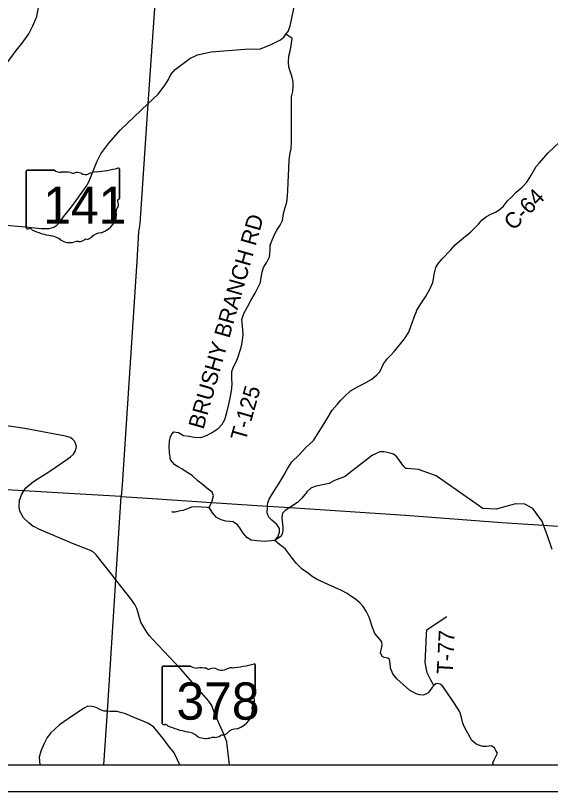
# Model space of a CAD drawing. Extents: x 0 to 34, y 0 to 22.
# Drawn here: x 4.206 to 6.219, y 14 to 16.922 of the extents above; entities that cross this region are included whole.
import ezdxf

# ---------------------------------------------------------------- set-up
doc = ezdxf.new("R2010")
doc.units = 0
for name, color, linetype in [('GM_X_County_Road', 7, 'Continuous'), ('GM_X_County_Road_Text', 7, 'Continuous'), ('GM_X_State_Route', 7, 'Continuous'), ('GM_X_State_Shield', 7, 'Continuous'), ('GM_X_Township', 7, 'Continuous'), ('GM_X_Township_Road', 7, 'Continuous'), ('GM_X_Township_Road_Text', 7, 'Continuous'), ('SH_Data', 7, 'Continuous'), ('SH_Masking', 7, 'Continuous')]:
    doc.layers.add(name, color=color, linetype=linetype)

msp = doc.modelspace()

# ---------------------------------------------------------------- linework, layer by layer
at = {"layer": 'GM_X_County_Road'}
for points in [[(4.0336, 16.5466), (4.0388, 16.5536), (4.0613, 16.5797), (4.0854, 16.6142), (4.1095, 16.6497), (4.1485, 16.7065), (4.1848, 16.7572), (4.2085, 16.7901), (4.231, 16.8177), (4.2555, 16.8525), (4.2704, 16.8828), (4.2862, 16.9173), (4.2952, 16.9655)], [(5.7143, 15.8076), (5.7144, 15.8078), (5.7163, 15.8125), (5.7312, 15.8359), (5.7484, 15.862), (5.7664, 15.8931), (5.7764, 15.9166), (5.783, 15.9522), (5.7881, 15.9723), (5.7946, 15.9852), (5.8118, 16.0056), (5.8434, 16.0397), (5.8602, 16.0582), (5.877, 16.0721), (5.8915, 16.085), (5.9185, 16.1053), (5.9483, 16.136), (5.9608, 16.1507), (5.9776, 16.1647), (5.994, 16.1741), (6.0126, 16.1812), (6.024, 16.1884), (6.0419, 16.2038), (6.0576, 16.2235), (6.074, 16.239), (6.0904, 16.2567), (6.1121, 16.2749), (6.13, 16.2941), (6.1415, 16.3116), (6.1645, 16.3532), (6.1774, 16.3668), (6.2103, 16.4042), (6.2518, 16.4439)], [(5.1525, 15.0518), (5.1525, 15.0521), (5.1536, 15.0684), (5.1541, 15.0746), (5.1552, 15.0862), (5.1598, 15.101), (5.1782, 15.1298), (5.1981, 15.1608), (5.2168, 15.1926), (5.2264, 15.2115), (5.2452, 15.2411), (5.2718, 15.2656), (5.2966, 15.2932), (5.3267, 15.3212), (5.3451, 15.3495), (5.373, 15.3957), (5.3972, 15.4355), (5.4159, 15.4574), (5.43, 15.4729), (5.4449, 15.4884), (5.4658, 15.5088), (5.4947, 15.525), (5.5179, 15.5359), (5.5465, 15.5528), (5.5659, 15.5683), (5.5762, 15.5796), (5.5911, 15.6099), (5.6053, 15.63), (5.6179, 15.6428), (5.6316, 15.6576), (5.6694, 15.7037), (5.6858, 15.7298), (5.6939, 15.7503), (5.7055, 15.7863), (5.7143, 15.8076)], [(6.0042, 14.1), (6.0021, 14.1076), (6.0067, 14.1193), (6.0197, 14.1447), (6.0137, 14.1546), (6.0077, 14.1649), (5.9956, 14.1718), (5.9786, 14.1689), (5.9645, 14.1697), (5.9524, 14.1732), (5.9384, 14.1797), (5.9229, 14.1923), (5.8944, 14.2441), (5.8892, 14.2567), (5.884, 14.2788), (5.8777, 14.2993), (5.8574, 14.3317), (5.8258, 14.3774), (5.8115, 14.3988), (5.8032, 14.4038), (5.7956, 14.4061), (5.7869, 14.405), (5.7804, 14.3988), (5.775, 14.3937), (5.764, 14.3781), (5.759, 14.3713), (5.7502, 14.3661), (5.74, 14.3631), (5.7263, 14.3635), (5.7135, 14.3674), (5.6878, 14.3812), (5.6406, 14.4236), (5.6263, 14.4434), (5.6173, 14.4644), (5.6155, 14.4826), (5.6129, 14.4963), (5.6065, 14.5016), (5.5933, 14.5044), (5.585, 14.5086), (5.579, 14.5215), (5.5836, 14.5386), (5.5856, 14.5515), (5.5841, 14.5618), (5.5804, 14.5686), (5.5578, 14.5946), (5.5488, 14.6178), (5.5365, 14.6558), (5.5252, 14.6787), (5.5143, 14.6958), (5.5019, 14.7103), (5.4857, 14.7245), (5.4672, 14.7356), (5.4539, 14.7451), (5.432, 14.7566), (5.3844, 14.7774), (5.3409, 14.7985), (5.3227, 14.8092), (5.3084, 14.8211), (5.285, 14.8368), (5.2733, 14.8486), (5.2616, 14.8597), (5.2484, 14.8776), (5.2334, 14.8974), (5.2221, 14.9119), (5.2126, 14.9192), (5.1994, 14.9295), (5.1821, 14.9448), (5.1935, 14.9588), (5.1993, 14.9766), (5.199, 14.9899), (5.1885, 15.0055), (5.1707, 15.0212), (5.1591, 15.0334), (5.1523, 15.0482), (5.1525, 15.0518)]]:
    msp.add_lwpolyline(points, dxfattribs=at)
at = {"layer": 'GM_X_State_Route'}
for points in [[(4.1718, 16.1317), (4.2417, 16.1257), (4.3026, 16.1199), (4.3322, 16.1199), (4.3497, 16.1251), (4.3613, 16.1316), (4.3714, 16.1428), (4.3864, 16.1636), (4.4217, 16.2075), (4.4718, 16.2779), (4.4817, 16.2958), (4.5114, 16.371), (4.5266, 16.4005), (4.5566, 16.4415), (4.6011, 16.4915), (4.704, 16.5887), (4.7423, 16.6248), (4.7691, 16.6605), (4.781, 16.6803), (4.7898, 16.6995), (4.8063, 16.7188), (4.8612, 16.7594), (4.8904, 16.7735), (4.9423, 16.7854), (5.0684, 16.7946), (5.1279, 16.796), (5.1704, 16.8131), (5.2024, 16.8305), (5.2159, 16.8404), (5.2234, 16.8516), (5.2313, 16.8616), (5.2394, 16.8822), (5.2446, 16.9056), (5.2543, 16.9547)], [(5.0108, 14.1), (5.002, 14.1738), (5.0005, 14.1872), (4.9899, 14.2155), (4.9574, 14.2889), (4.9495, 14.3081), (4.9439, 14.3238), (4.9333, 14.3404), (4.8282, 14.4609), (4.7209, 14.5739), (4.7088, 14.5871), (4.7004, 14.5998), (4.6779, 14.6376), (4.6723, 14.6534), (4.6668, 14.6729), (4.6619, 14.6889), (4.6551, 14.7043), (4.6401, 14.7256), (4.5837, 14.7973), (4.5672, 14.8182), (4.5089, 14.8904), (4.4989, 14.9009), (4.4877, 14.9069), (4.4199, 14.9341), (4.2932, 14.988), (4.2791, 14.9947), (4.2722, 14.998), (4.2552, 15.011), (4.2356, 15.0305), (4.2222, 15.0548), (4.2193, 15.0723), (4.2207, 15.0962), (4.2293, 15.1195), (4.2374, 15.1315), (4.2451, 15.143), (4.2738, 15.1669), (4.3351, 15.2062), (4.3946, 15.2468), (4.4131, 15.26), (4.4236, 15.2703), (4.4316, 15.2822), (4.4347, 15.2992), (4.4316, 15.3115), (4.4272, 15.3192), (4.4206, 15.3269), (4.4117, 15.3329), (4.394, 15.3379), (4.2405, 15.367), (4.1023, 15.3866)]]:
    msp.add_lwpolyline(points, dxfattribs=at)
at = {"layer": 'GM_X_State_Shield'}
for p, q in [((4.2463, 16.335), (4.2463, 16.1225)), ((4.3523, 16.3387), (4.2498, 16.3387)), ((4.5964, 16.2328), (4.5964, 16.344)), ((4.5964, 16.2328), (4.5964, 16.2328)), ((4.758, 14.468), (4.758, 14.2554)), ((4.8639, 14.4717), (4.7614, 14.4717)), ((5.108, 14.3657), (5.108, 14.4769)), ((5.108, 14.3658), (5.108, 14.3657))]:
    msp.add_line(p, q, dxfattribs=at)
for centre, major_axis, start_param, end_param in [((4.2503, 16.3355), (0.00406, 0), 1.712693, 3.28349), ((4.3767, 16.3634), (0.0393, 0), 4.042523, 4.731795), ((4.3898, 16.2194), (0.1412, 0), 1.404758, 1.657858), ((4.4385, 16.312), (0.0236, 0), 0.950623, 2.079405), ((4.5191, 16.2738), (0.0747, 0), 1.699011, 2.107814), ((4.4717, 16.6285), (0.3713, 0), 4.814394, 5.042369), ((4.5925, 16.3444), (0.0039, 0), 6.141152, 7.989035), ((4.4218, 16.3366), (0.0113, 0), 3.836095, 5.185415), ((4.4689, 16.3457), (0.0284, 0), 4.081561, 5.145723), ((4.5955, 16.2246), (0.00603, 0), 1.883978, 3.671073), ((4.5571, 16.2105), (0.0362, 0), 5.934695, 6.695948), ((4.5923, 16.2323), (0.00417, 0), 5.05454, 6.418171), ((4.6104, 16.1862), (0.0263, 0), 2.387724, 3.262537), ((4.4925, 16.1721), (0.0929, 0), 5.101752, 6.440018), ((4.2504, 16.122), (0.00409, 0), 3.00124, 4.508301), ((4.251, 16.1437), (0.0312, 0), 4.665946, 4.897461), ((4.2574, 16.1102), (0.0113, 0), 0.519207, 1.627899), ((4.3995, 16.3012), (0.2681, 0), 4.195997, 4.488961), ((4.5317, 16.0628), (0.0509, 0), 1.647645, 2.488434), ((4.3196, 16.027), (0.0839, 0), 0.823519, 1.323587), ((4.4103, 16.1091), (0.0532, 0), 4.026481, 4.996735), ((4.4411, 16.0356), (0.0437, 0), 1.495662, 1.94098), ((4.445, 16.0932), (0.0284, 0), 4.691044, 5.507374), ((4.4706, 16.0726), (0.00798, 0), 1.147584, 2.315152), ((4.4672, 16.1019), (0.03, 0), 4.937069, 5.64225), ((4.762, 14.4684), (0.00406, 0), 1.712693, 3.28349), ((4.8883, 14.4963), (0.0393, 0), 4.042523, 4.731795), ((4.9014, 14.3523), (0.1412, 0), 1.404758, 1.657858), ((4.9334, 14.4696), (0.0113, 0), 3.836095, 5.185415), ((4.9501, 14.445), (0.0236, 0), 0.950623, 2.079405), ((5.0307, 14.4067), (0.0747, 0), 1.699011, 2.107814), ((4.9833, 14.7615), (0.3713, 0), 4.814394, 5.042369), ((5.1042, 14.4774), (0.0039, 0), 6.141152, 7.989035), ((4.9806, 14.4787), (0.0284, 0), 4.081561, 5.145723), ((5.1071, 14.3576), (0.00603, 0), 1.883978, 3.671073), ((5.0688, 14.3435), (0.0362, 0), 5.934695, 6.695948), ((5.1039, 14.3653), (0.00417, 0), 5.05454, 6.418171), ((5.0041, 14.305), (0.0929, 0), 5.101752, 6.440018), ((5.122, 14.3192), (0.0263, 0), 2.387724, 3.262537), ((4.762, 14.255), (0.00409, 0), 3.00124, 4.508301), ((4.7626, 14.2767), (0.0312, 0), 4.665946, 4.897461), ((4.769, 14.2432), (0.0113, 0), 0.519207, 1.627899), ((4.9112, 14.4341), (0.2681, 0), 4.195997, 4.488961), ((5.0433, 14.1957), (0.0509, 0), 1.647645, 2.488434), ((4.8312, 14.1599), (0.0839, 0), 0.823519, 1.323587), ((4.922, 14.2421), (0.0532, 0), 4.026481, 4.996735), ((4.9527, 14.1686), (0.0437, 0), 1.495662, 1.94098), ((4.9566, 14.2262), (0.0284, 0), 4.691044, 5.507374), ((4.9823, 14.2056), (0.00798, 0), 1.147584, 2.315152), ((4.9788, 14.2348), (0.03, 0), 4.937069, 5.64225)]:
    msp.add_ellipse(centre, major_axis=major_axis, ratio=0.8, start_param=start_param, end_param=end_param, dxfattribs=at)
at = {"layer": 'GM_X_Township'}
for points in [[(4.7383, 17.0951), (4.704, 16.5887), (4.6735, 16.1378), (4.6688, 16.1067), (4.6617, 15.9964), (4.6068, 15.1539), (4.6039, 15.1106), (4.4494, 15.1194), (4.2374, 15.1315), (3.9258, 15.1493), (3.6093, 15.1673), (3.5571, 15.1752), (3.5118, 15.1797), (3.2794, 15.1952), (2.59, 15.2415), (2.4159, 15.2489), (2.1, 15.2699)], [(4.5386, 14.1), (4.5516, 14.3018), (4.5837, 14.7973), (4.6039, 15.1106), (4.7025, 15.1042), (4.9432, 15.0884), (5.1541, 15.0746), (5.2376, 15.0692), (5.6728, 15.0407), (6.0364, 15.013), (6.1929, 15.0025), (6.375, 14.9903), (6.7178, 14.9672), (7.6051, 14.9095), (7.6512, 14.9069), (8.0847, 14.8753), (8.8343, 14.8293), (8.9, 14.8252)]]:
    msp.add_lwpolyline(points, dxfattribs=at)
at = {"layer": 'GM_X_Township_Road'}
for points in [[(5.2339, 16.3409), (5.2339, 16.341), (5.2343, 16.347), (5.2356, 16.3754), (5.2384, 16.3974), (5.2435, 16.421), (5.2443, 16.4434), (5.2438, 16.4855), (5.2445, 16.5379), (5.2439, 16.5675), (5.2437, 16.5915), (5.2449, 16.6158), (5.2492, 16.6359), (5.2508, 16.653), (5.2505, 16.6712), (5.2469, 16.6898), (5.2405, 16.7085), (5.2349, 16.7275), (5.2331, 16.7453), (5.2337, 16.7685), (5.2387, 16.7878), (5.2434, 16.8083), (5.2461, 16.8265), (5.2469, 16.8349), (5.2234, 16.8516)], [(4.9345, 15.068), (4.9432, 15.0884), (4.9455, 15.0938), (4.9506, 15.1127), (4.9453, 15.1264), (4.9257, 15.1425), (4.9068, 15.1581), (4.8929, 15.1685), (4.8706, 15.1902), (4.8476, 15.204), (4.8317, 15.2143), (4.8181, 15.2224), (4.8049, 15.2293), (4.7887, 15.2484), (4.7847, 15.2761), (4.7844, 15.2993), (4.7853, 15.3186), (4.7892, 15.3361), (4.7934, 15.3452), (4.8021, 15.3542), (4.8188, 15.3519), (4.8377, 15.3408), (4.8589, 15.3372), (4.8786, 15.3337), (4.9029, 15.3321), (4.9245, 15.3399), (4.9462, 15.3512), (4.9683, 15.3667), (4.9839, 15.3829), (4.9939, 15.4003), (5.0024, 15.4322), (5.009, 15.4588), (5.0141, 15.4811), (5.0188, 15.5084), (5.0204, 15.5324), (5.0202, 15.5567), (5.0203, 15.5814), (5.0265, 15.5988), (5.0361, 15.6181), (5.0434, 15.6367), (5.048, 15.653), (5.0549, 15.6712), (5.0604, 15.6981), (5.062, 15.7205), (5.0603, 15.7536), (5.0578, 15.7771), (5.0648, 15.8002), (5.0782, 15.8249), (5.0912, 15.8491), (5.1073, 15.8763), (5.1214, 15.9032), (5.1276, 15.9169), (5.1284, 15.9279), (5.1343, 15.9552), (5.1393, 15.9734), (5.1519, 15.9927), (5.1615, 16.0132), (5.1643, 16.0367), (5.164, 16.0568), (5.1717, 16.0758), (5.1814, 16.1), (5.1886, 16.1137), (5.2016, 16.1322), (5.2101, 16.1492), (5.2148, 16.1762), (5.2206, 16.1986), (5.2264, 16.2183), (5.2292, 16.2414), (5.2304, 16.2634), (5.2321, 16.29), (5.2327, 16.3223), (5.2339, 16.3409)], [(6.1915, 15.0062), (6.1871, 15.0177), (6.1792, 15.0284), (6.1521, 15.065), (6.123, 15.0816), (6.0873, 15.0828), (6.0151, 15.0634), (5.9645, 15.0657), (5.7891, 15.1889), (5.7228, 15.2128), (5.6791, 15.2157), (5.6742, 15.2165), (5.6674, 15.2232), (5.6408, 15.2598), (5.6288, 15.2701), (5.616, 15.2741), (5.5928, 15.2786), (5.5767, 15.2785), (5.5599, 15.2718), (5.5488, 15.266), (5.4595, 15.1974), (5.4458, 15.1861), (5.4065, 15.171), (5.3862, 15.1592), (5.3369, 15.1501), (5.3263, 15.1461), (5.3169, 15.1422), (5.3021, 15.1279), (5.2968, 15.1211)], [(5.2968, 15.1211), (5.294, 15.1176), (5.2836, 15.1044), (5.2669, 15.0885), (5.2376, 15.0692), (5.2207, 15.0581), (5.2102, 15.0484), (5.208, 15.0313), (5.2118, 14.993), (5.2114, 14.9841), (5.2107, 14.9732), (5.2057, 14.9611), (5.1821, 14.9448)], [(4.8454, 15.0614), (4.8371, 15.0583), (4.8269, 15.0563), (4.8064, 15.0522), (4.7961, 15.0522), (4.7945, 15.0524)], [(4.9489, 15.0463), (4.9483, 15.047), (4.9393, 15.0611), (4.9345, 15.068), (4.9271, 15.0686), (4.8866, 15.0717), (4.8679, 15.0707), (4.8535, 15.0645), (4.8454, 15.0614)], [(5.1821, 14.9448), (5.143, 14.9412), (5.1157, 14.9432), (5.093, 14.9468), (5.0759, 14.956), (5.0601, 14.9758), (5.0496, 14.9922), (5.041, 15.0036), (5.0247, 15.0147), (4.9978, 15.0172), (4.9793, 15.0226), (4.9619, 15.0314), (4.9489, 15.0463)], [(6.2253, 14.9114), (6.207, 14.9657), (6.1929, 15.0025), (6.1915, 15.0062)], [(5.7804, 14.3988), (5.7669, 14.4214), (5.7549, 14.4462), (5.7475, 14.485), (5.7493, 14.5343), (5.753, 14.592), (5.7539, 14.6091), (5.8266, 14.657), (5.8295, 14.6588)], [(4.616, 14.293), (4.6157, 14.2931), (4.6059, 14.2964), (4.5885, 14.3007), (4.5612, 14.3012), (4.5516, 14.3018), (4.5399, 14.3025), (4.5259, 14.3079), (4.5093, 14.3167), (4.4945, 14.3198), (4.4778, 14.3206), (4.4642, 14.3135), (4.4242, 14.2875), (4.3713, 14.2505), (4.3385, 14.2207), (4.3244, 14.2029), (4.3129, 14.1802), (4.3013, 14.1521), (4.2948, 14.1294), (4.2966, 14.1)], [(4.8236, 14.1), (4.8236, 14.1), (4.8149, 14.1191), (4.8033, 14.145), (4.7819, 14.1717), (4.7608, 14.1995), (4.7438, 14.2212), (4.7265, 14.2422), (4.7061, 14.2564), (4.68, 14.2668), (4.6509, 14.2787), (4.6229, 14.2906), (4.616, 14.293)]]:
    msp.add_lwpolyline(points, dxfattribs=at)
at = {"layer": 'SH_Data'}
for p, q in [((2.1, 14.1), (8.9, 14.1)), ((2, 14), (9, 14))]:
    msp.add_line(p, q, dxfattribs=at)
at = {"layer": 'SH_Masking'}
for p, q in [((4.2463, 16.1225), (4.2463, 16.335)), ((4.2498, 16.3387), (4.3523, 16.3387)), ((4.5964, 16.344), (4.5964, 16.2328)), ((4.5937, 16.2292), (4.5937, 16.2292)), ((4.7579, 14.2554), (4.7579, 14.468)), ((4.7614, 14.4717), (4.8639, 14.4717)), ((5.108, 14.4769), (5.108, 14.3657)), ((5.1053, 14.3622), (5.1053, 14.3622))]:
    msp.add_line(p, q, dxfattribs=at)
for centre, major_axis, start_param, end_param in [((4.2503, 16.3355), (0.00406, 0), 1.712693, 3.28349), ((4.3767, 16.3634), (0.0393, 0), 4.042523, 4.731795), ((4.3898, 16.2194), (0.1412, 0), 1.404758, 1.657858), ((4.4385, 16.312), (0.0236, 0), 0.950623, 2.079405), ((4.5191, 16.2738), (0.0747, 0), 1.699011, 2.107814), ((4.4717, 16.6285), (0.3713, 0), 4.814394, 5.042369), ((4.5925, 16.3444), (0.0039, 0), 6.141152, 7.989035), ((4.4218, 16.3366), (0.0113, 0), 3.836095, 5.185415), ((4.4689, 16.3457), (0.0284, 0), 4.081561, 5.145723), ((4.5955, 16.2246), (0.00603, 0), 1.883978, 3.671073), ((4.5571, 16.2105), (0.0362, 0), 5.934695, 6.695948), ((4.5923, 16.2323), (0.00417, 0), 5.05454, 6.418171), ((4.6104, 16.1862), (0.0263, 0), 2.387724, 3.262537), ((4.4925, 16.1721), (0.0929, 0), 5.101752, 6.440018), ((4.2504, 16.122), (0.00409, 0), 3.00124, 4.508301), ((4.251, 16.1437), (0.0312, 0), 4.665946, 4.897461), ((4.2574, 16.1102), (0.0113, 0), 0.519207, 1.627899), ((4.3995, 16.3012), (0.2681, 0), 4.195997, 4.488961), ((4.5317, 16.0628), (0.0509, 0), 1.647645, 2.488434), ((4.3196, 16.027), (0.0839, 0), 0.823519, 1.323587), ((4.4103, 16.1091), (0.0532, 0), 4.026481, 4.996735), ((4.4411, 16.0356), (0.0437, 0), 1.495662, 1.94098), ((4.445, 16.0932), (0.0284, 0), 4.691044, 5.507374), ((4.4706, 16.0726), (0.00798, 0), 1.147584, 2.315152), ((4.4672, 16.1019), (0.03, 0), 4.937069, 5.64225), ((4.762, 14.4684), (0.00406, 0), 1.712693, 3.28349), ((4.8883, 14.4963), (0.0393, 0), 4.042523, 4.731795), ((4.9014, 14.3523), (0.1412, 0), 1.404758, 1.657858), ((4.9334, 14.4696), (0.0113, 0), 3.836095, 5.185415), ((4.9501, 14.445), (0.0236, 0), 0.950623, 2.079405), ((5.0307, 14.4067), (0.0747, 0), 1.699011, 2.107814), ((4.9833, 14.7615), (0.3713, 0), 4.814394, 5.042369), ((5.1042, 14.4774), (0.0039, 0), 6.141152, 7.989035), ((4.9806, 14.4787), (0.0284, 0), 4.081561, 5.145723), ((5.1071, 14.3576), (0.00603, 0), 1.883978, 3.671073), ((5.0688, 14.3435), (0.0362, 0), 5.934695, 6.695948), ((5.1039, 14.3653), (0.00417, 0), 5.05454, 6.418171), ((5.0041, 14.305), (0.0929, 0), 5.101752, 6.440018), ((5.122, 14.3192), (0.0263, 0), 2.387724, 3.262537), ((4.762, 14.255), (0.00409, 0), 3.00124, 4.508301), ((4.7626, 14.2767), (0.0312, 0), 4.665946, 4.897461), ((4.769, 14.2432), (0.0113, 0), 0.519207, 1.627899), ((4.9112, 14.4341), (0.2681, 0), 4.195997, 4.488961), ((5.0433, 14.1957), (0.0509, 0), 1.647645, 2.488434), ((4.8312, 14.1599), (0.0839, 0), 0.823519, 1.323587), ((4.922, 14.2421), (0.0532, 0), 4.026481, 4.996735), ((4.9527, 14.1686), (0.0437, 0), 1.495662, 1.94098), ((4.9566, 14.2262), (0.0284, 0), 4.691044, 5.507374), ((4.9823, 14.2056), (0.00798, 0), 1.147584, 2.315152), ((4.9788, 14.2348), (0.03, 0), 4.937069, 5.64225)]:
    msp.add_ellipse(centre, major_axis=major_axis, ratio=0.8, start_param=start_param, end_param=end_param, dxfattribs=at)

# ---------------------------------------------------------------- texts
at = {"layer": 'GM_X_County_Road_Text'}
msp.add_text('C-64', height=0.06, rotation=45.7104, dxfattribs=at).set_placement((6.08, 16.1091))
at = {"layer": 'GM_X_State_Shield'}
for s, p in [('141', (4.3102, 16.1375)), ('378', (4.8114, 14.2704))]:
    msp.add_text(s, height=0.14004, dxfattribs=at).set_placement(p)
at = {"layer": 'GM_X_Township_Road_Text'}
for s, rotation, p in [('BRUSHY BRANCH RD', 74.1328, (4.9126, 15.3608)), ('T-125', 74.1328, (5.0713, 15.3157)), ('T-77', 87.0579, (5.8505, 14.4406))]:
    msp.add_text(s, height=0.06, rotation=rotation, dxfattribs=at).set_placement(p)

doc.saveas('drawing.dxf')
